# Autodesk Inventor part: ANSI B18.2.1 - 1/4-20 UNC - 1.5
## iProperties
Comments: To add or edit properties for Autodesk Inventor files, use iProperties.
Created: 2004-12
Part Number: ANSI B18.2.1 - 1/4-20 UNC - 1.5
Vendor: Autodesk Inc.
Document SubType Name: Modeling
Designer: John Blackburn
Material: Default
Description: Hex Cap Screw
Standard: ANSI B18.2.1
Alert: To add or edit properties for Autodesk Inventor files, use iProperties.
Control State: 0
Master: False
Checked Out: False
Shininess: 64.0
Length Units: 11272
Angle Units: 11279
Time Units: 11290
Mass Units: 11286
Length Display Precision: 3
Angle Display Precision: 2
Compacted: True
EGR: 3
Classification: un/spsc 31161513
Density: 0.0
Volumn: 0.0
Area: 0.0
PropertySet Name: Model Information
Author: John Blackburn
Revision Number: 8
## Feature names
1. Body [Revolution]
2. Head [Extrusion]
3. Chamfer1 [Revolution]
4. Chamfer2
